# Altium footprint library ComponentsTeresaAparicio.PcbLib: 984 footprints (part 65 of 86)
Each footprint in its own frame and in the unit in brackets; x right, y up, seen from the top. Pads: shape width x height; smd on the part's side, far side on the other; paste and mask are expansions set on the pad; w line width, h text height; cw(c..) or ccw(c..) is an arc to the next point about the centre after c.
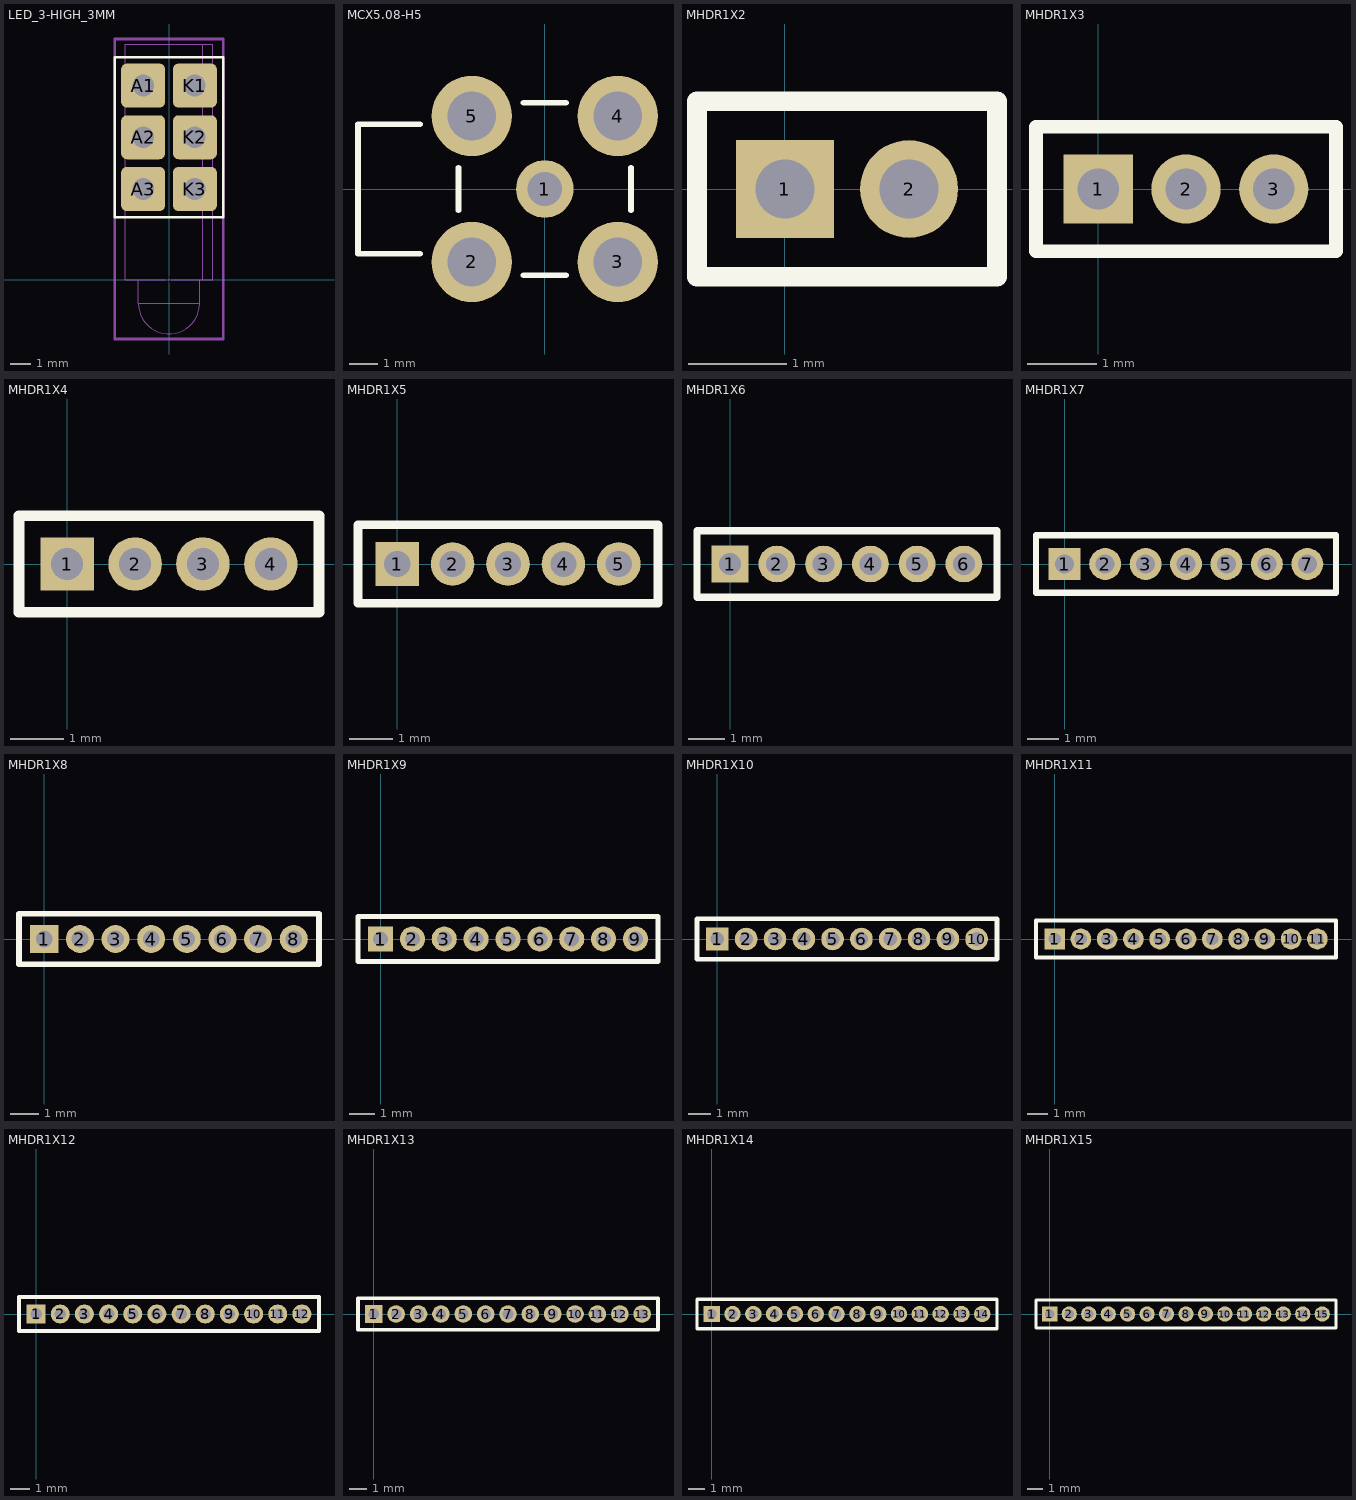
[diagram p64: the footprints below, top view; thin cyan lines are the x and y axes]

## LED_3-HIGH_3MM [mil] "LED Circuit Board Indicator Tri-Level"
height 600
pads (7):
  round 20 on Mech14: 0(0,0)
  rrect25% 85x85 hole 42: A1(-50,375) A2(-50,275) A3(-50,175) K1(50,375) K2(50,275) K3(50,175)
Top Overlay:
  lines w5: -105,120 -105,430 105,430 105,120 -105,120
Mechanical 13:
  lines w1.97: -59.06,0 -59.06,-46.06 ; 59.06,0 59.06,-46.06 ; 65.35,0 65.35,455.12 ; -59.06,-46.06 ccw(c0,-46.06) 59.06,-46.06 ; -59.06,-46.06 59.06,-46.06 ; -85.04,0 -85.04,455.12 85.04,455.12 85.04,0 -85.04,0
Mechanical 14:
  lines w5: -105,-115 -105,465 105,465 105,-115 -105,-115
3D body: height 600, standoff -144.88, extent -85.04,-105.11 85.04,455.12

## MCX5.08-H5 [mm] "Connector; RF Coaxial, MCX, Thru-Hole; 5 Position; Right-Angle"
height 5.85
pads (5):
  round 2 hole 1.2: 1(0,0)
  round 2.8 hole 1.7: 2(-2.54,-2.54) 3(2.54,-2.54) 4(2.54,2.54) 5(-2.54,2.54)
Top Overlay:
  lines w0.2: -4.34,-2.25 -6.5,-2.25 -6.5,2.25 -4.34,2.25 ; -3,-0.74 -3,0.74 ; -0.74,-3 0.74,-3 ; -0.74,3 0.74,3 ; 3,-0.74 3,0.74

## MHDR1X2 [mm] "Connector; Header; 2 Position"
pads (2):
  rect 1x1 hole 0.6: 1(0,0)
  round 1 hole 0.6: 2(1.27,0)
Top Overlay:
  lines w0.2: -0.9,-0.9 -0.9,0.9 2.17,0.9 2.17,-0.9 -0.9,-0.9

## MHDR1X3 [mm] "Connector; Header; 3 Position"
pads (3):
  rect 1x1 hole 0.6: 1(0,0)
  round 1 hole 0.6: 2(1.27,0) 3(2.54,0)
Top Overlay:
  lines w0.2: -0.9,-0.9 3.44,-0.9 3.44,0.9 -0.9,0.9 -0.9,-0.9

## MHDR1X4 [mm] "Connector; Header; 4 Position"
pads (4):
  rect 1x1 hole 0.6: 1(0,0)
  round 1 hole 0.6: 2(1.27,0) 3(2.54,0) 4(3.81,0)
Top Overlay:
  lines w0.2: -0.9,-0.9 -0.9,0.9 4.71,0.9 4.71,-0.9 -0.9,-0.9

## MHDR1X5 [mm] "Connector; Header; 5 Position"
pads (5):
  rect 1x1 hole 0.6: 1(0,0)
  round 1 hole 0.6: 2(1.27,0) 3(2.54,0) 4(3.81,0) 5(5.08,0)
Top Overlay:
  lines w0.2: -0.9,-0.9 -0.9,0.9 5.98,0.9 5.98,-0.9 -0.9,-0.9

## MHDR1X6 [mm] "Connector; Header; 6 Position"
pads (6):
  rect 1x1 hole 0.6: 1(0,0)
  round 1 hole 0.6: 2(1.27,0) 3(2.54,0) 4(3.81,0) 5(5.08,0) 6(6.35,0)
Top Overlay:
  lines w0.2: -0.9,-0.9 7.25,-0.9 7.25,0.9 -0.9,0.9 -0.9,-0.9

## MHDR1X7 [mm] "Connector; Header; 7 Position"
pads (7):
  rect 1x1 hole 0.6: 1(0,0)
  round 1 hole 0.6: 2(1.27,0) 3(2.54,0) 4(3.81,0) 5(5.08,0) 6(6.35,0) 7(7.62,0)
Top Overlay:
  lines w0.2: -0.9,-0.9 -0.9,0.9 8.52,0.9 8.52,-0.9 -0.9,-0.9

## MHDR1X8 [mm] "Connector; Header; 8 Position"
pads (8):
  rect 1x1 hole 0.6: 1(0,0)
  round 1 hole 0.6: 2(1.27,0) 3(2.54,0) 4(3.81,0) 5(5.08,0) 6(6.35,0) 7(7.62,0) 8(8.89,0)
Top Overlay:
  lines w0.2: -0.9,-0.9 -0.9,0.9 9.79,0.9 9.79,-0.9 -0.9,-0.9

## MHDR1X9 [mm] "Connector; Header; 9 Position"
pads (9):
  rect 1x1 hole 0.6: 1(0,0)
  round 1 hole 0.6: 2(1.27,0) 3(2.54,0) 4(3.81,0) 5(5.08,0) 6(6.35,0) 7(7.62,0) 8(8.89,0) 9(10.16,0)
Top Overlay:
  lines w0.2: -0.9,-0.9 11.06,-0.9 11.06,0.9 -0.9,0.9 -0.9,-0.9

## MHDR1X10 [mm] "Connector; Header; 10 Position"
pads (10):
  rect 1x1 hole 0.6: 1(0,0)
  round 1 hole 0.6: 2(1.27,0) 3(2.54,0) 4(3.81,0) 5(5.08,0) 6(6.35,0) 7(7.62,0) 8(8.89,0) 9(10.16,0) 10(11.43,0)
Top Overlay:
  lines w0.2: -0.9,-0.9 -0.9,0.9 12.33,0.9 12.33,-0.9 -0.9,-0.9

## MHDR1X11 [mm] "Connector; Header; 11 Position"
pads (11):
  rect 1x1 hole 0.6: 1(0,0)
  round 1 hole 0.6: 2(1.27,0) 3(2.54,0) 4(3.81,0) 5(5.08,0) 6(6.35,0) 7(7.62,0) 8(8.89,0) 9(10.16,0) 10(11.43,0) 11(12.7,0)
Top Overlay:
  lines w0.2: -0.9,-0.9 13.6,-0.9 13.6,0.9 -0.9,0.9 -0.9,-0.9

## MHDR1X12 [mm] "Connector; Header; 12 Position"
pads (12):
  rect 1x1 hole 0.6: 1(0,0)
  round 1 hole 0.6: 2(1.27,0) 3(2.54,0) 4(3.81,0) 5(5.08,0) 6(6.35,0) 7(7.62,0) 8(8.89,0) 9(10.16,0) 10(11.43,0) 11(12.7,0) 12(13.97,0)
Top Overlay:
  lines w0.2: -0.9,-0.9 -0.9,0.9 14.87,0.9 14.87,-0.9 -0.9,-0.9

## MHDR1X13 [mm] "Connector; Header; 13 Position"
pads (13):
  rect 1x1 hole 0.6: 1(0,0)
  round 1 hole 0.6: 2(1.27,0) 3(2.54,0) 4(3.81,0) 5(5.08,0) 6(6.35,0) 7(7.62,0) 8(8.89,0) 9(10.16,0) 10(11.43,0) 11(12.7,0) 12(13.97,0) 13(15.24,0)
Top Overlay:
  lines w0.2: -0.9,-0.9 -0.9,0.9 16.14,0.9 16.14,-0.9 -0.9,-0.9

## MHDR1X14 [mm] "Connector; Header; 14 Position"
pads (14):
  rect 1x1 hole 0.6: 1(0,0)
  round 1 hole 0.6: 2(1.27,0) 3(2.54,0) 4(3.81,0) 5(5.08,0) 6(6.35,0) 7(7.62,0) 8(8.89,0) 9(10.16,0) 10(11.43,0) 11(12.7,0) 12(13.97,0) 13(15.24,0) 14(16.51,0)
Top Overlay:
  lines w0.2: -0.9,-0.9 -0.9,0.9 17.41,0.9 17.41,-0.9 -0.9,-0.9

## MHDR1X15 [mm] "Connector; Header; 15 Position"
pads (15):
  rect 1x1 hole 0.6: 1(0,0)
  round 1 hole 0.6: 2(1.27,0) 3(2.54,0) 4(3.81,0) 5(5.08,0) 6(6.35,0) 7(7.62,0) 8(8.89,0) 9(10.16,0) 10(11.43,0) 11(12.7,0) 12(13.97,0) 13(15.24,0) 14(16.51,0) 15(17.78,0)
Top Overlay:
  lines w0.2: -0.9,-0.9 -0.9,0.9 18.68,0.9 18.68,-0.9 -0.9,-0.9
